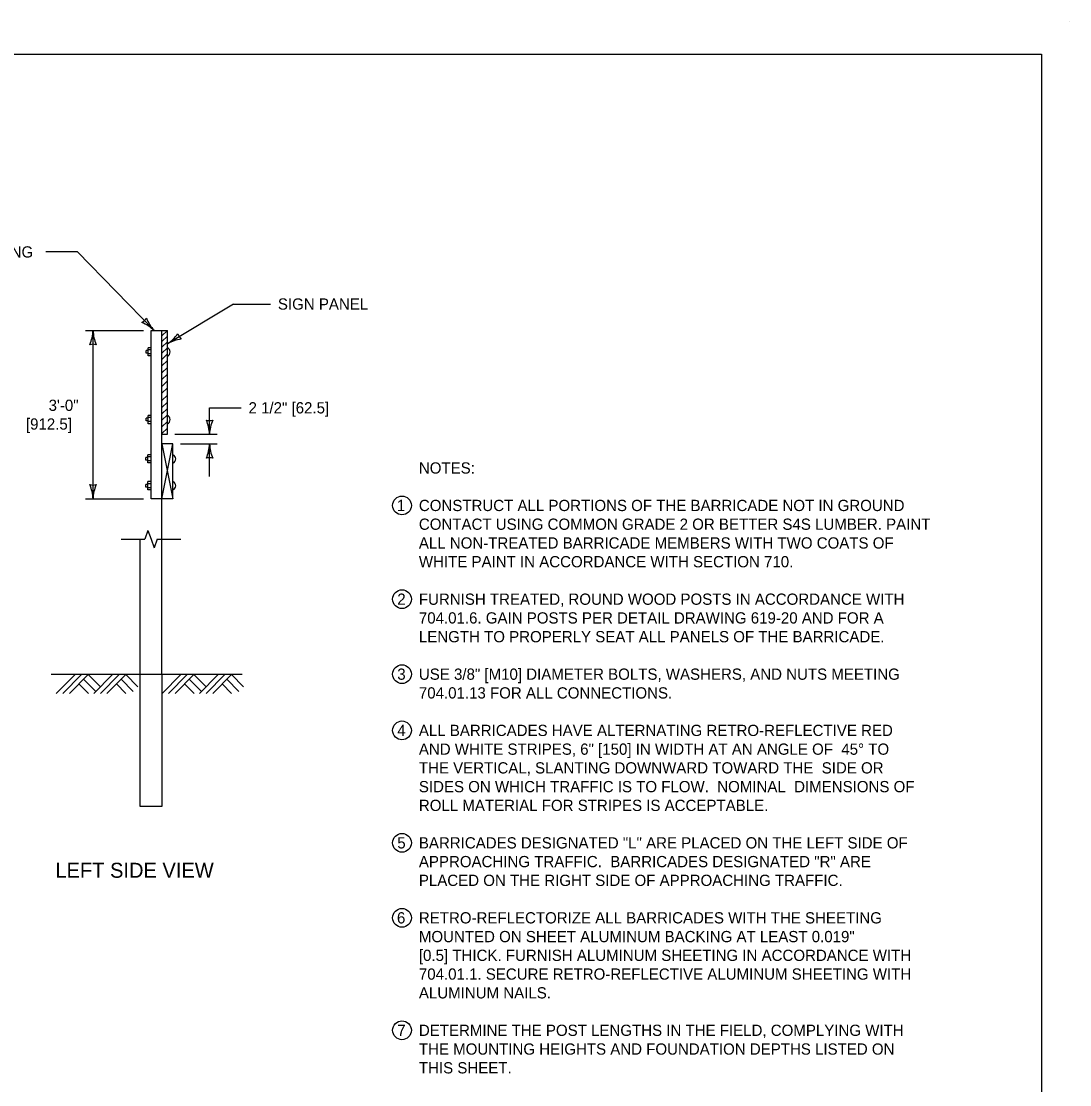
# Model space of a CAD drawing. Extents: x 49991.4 to 50021, y 49987.6 to 50011.4.
# Drawn here: x 50011.31 to 50016.9, y 49993.5 to 49999.18 of the extents above; entities that cross this region are included whole.
import ezdxf

# ---------------------------------------------------------------- set-up
doc = ezdxf.new("R2010")
doc.units = 0
for name, color, linetype in [('Level 1', 7, 'Continuous'), ('Level 2', 7, 'Continuous'), ('Level 3', 7, 'Continuous'), ('Level 4', 7, 'Continuous'), ('Level 6', 7, 'Continuous')]:
    doc.layers.add(name, color=color, linetype=linetype)

msp = doc.modelspace()

# ---------------------------------------------------------------- linework, layer by layer
at = {"layer": 'Level 1'}
for p, q in [((50016.9001, 49999.1756), (50016.9001, 49999.1756)), ((50012.0001, 49997.5261), (50012.0874, 49997.5261)), ((50012.0001, 49996.6277), (50012.0001, 49997.5261)), ((50012.0586, 49996.9206), (50012.0586, 49997.5261)), ((50012.0874, 49997.5261), (50012.0586, 49997.4973)), ((50012.0874, 49996.9724), (50012.0874, 49997.5261)), ((50012.0874, 49997.4958), (50012.0586, 49997.467)), ((50012.0874, 49997.4658), (50012.0586, 49997.437)), ((50011.9738, 49997.4045), (50011.9738, 49997.4195)), ((50011.9852, 49997.4195), (50011.9738, 49997.4195)), ((50011.9852, 49997.4045), (50011.9738, 49997.4045)), ((50012.0001, 49997.434), (50011.9852, 49997.434)), ((50011.9852, 49997.39), (50011.9852, 49997.434)), ((50012.0001, 49997.423), (50011.9852, 49997.423)), ((50012.0001, 49997.401), (50011.9852, 49997.401)), ((50012.0001, 49997.39), (50011.9852, 49997.39)), ((50012.0874, 49997.4329), (50012.0586, 49997.4041)), ((50012.0874, 49997.4005), (50012.0586, 49997.3717)), ((50012.0874, 49997.3658), (50012.0586, 49997.337)), ((50012.0874, 49997.3282), (50012.0586, 49997.2994)), ((50012.0874, 49997.2924), (50012.0586, 49997.2636)), ((50012.0874, 49997.2565), (50012.0586, 49997.2277)), ((50012.0874, 49997.2196), (50012.0586, 49997.1908)), ((50012.0874, 49997.1814), (50012.0586, 49997.1526)), ((50012.0874, 49997.1444), (50012.0586, 49997.1156)), ((50012.0874, 49997.1106), (50012.0586, 49997.0818)), ((50011.9738, 49997.0433), (50011.9738, 49997.0583)), ((50011.9852, 49997.0583), (50011.9738, 49997.0583)), ((50012.0001, 49997.0728), (50011.9852, 49997.0728)), ((50011.9852, 49997.0288), (50011.9852, 49997.0728)), ((50012.0001, 49997.0618), (50011.9852, 49997.0618)), ((50012.0874, 49997.0763), (50012.0586, 49997.0475)), ((50011.9852, 49997.0433), (50011.9738, 49997.0433)), ((50012.0001, 49997.0398), (50011.9852, 49997.0398)), ((50012.0001, 49997.0288), (50011.9852, 49997.0288)), ((50012.0874, 49997.0406), (50012.0586, 49997.0118)), ((50012.0876, 49997.0052), (50012.0586, 49996.9762)), ((50012.0586, 49996.9724), (50012.0874, 49996.9724)), ((50012.0586, 49996.6277), (50012.1172, 49996.9206)), ((50012.0586, 49996.9206), (50012.1172, 49996.6277)), ((50012.0586, 49995.6901), (50012.0586, 49996.9206)), ((50012.1172, 49996.9206), (50012.0586, 49996.9206)), ((50012.1172, 49996.6277), (50012.1172, 49996.9206)), ((50011.9726, 49996.8336), (50011.9726, 49996.8486)), ((50011.984, 49996.8486), (50011.9726, 49996.8486)), ((50011.984, 49996.8336), (50011.9726, 49996.8336)), ((50012.0001, 49996.8631), (50011.984, 49996.8631)), ((50011.984, 49996.8191), (50011.984, 49996.8631)), ((50012.0001, 49996.8521), (50011.984, 49996.8521)), ((50012.0001, 49996.8301), (50011.984, 49996.8301)), ((50012.0001, 49996.8191), (50011.984, 49996.8191)), ((50012.0001, 49996.7196), (50011.984, 49996.7196)), ((50011.984, 49996.6756), (50011.984, 49996.7196)), ((50012.0001, 49996.7086), (50011.984, 49996.7086)), ((50011.9726, 49996.6901), (50011.9726, 49996.7051)), ((50011.984, 49996.7051), (50011.9726, 49996.7051)), ((50011.984, 49996.6901), (50011.9726, 49996.6901)), ((50012.0001, 49996.6866), (50011.984, 49996.6866)), ((50012.0001, 49996.6756), (50011.984, 49996.6756)), ((50012.1172, 49996.6277), (50012.0001, 49996.6277)), ((50011.9415, 49995.6901), (50011.9415, 49996.4123)), ((50012.4865, 49995.6901), (50011.4678, 49995.6901)), ((50011.4951, 49995.5901), (50011.5951, 49995.6901)), ((50011.5301, 49995.5901), (50011.6301, 49995.6901)), ((50011.5651, 49995.5901), (50011.6651, 49995.6901)), ((50011.6651, 49995.6901), (50011.7301, 49995.6251)), ((50011.6951, 49995.5901), (50011.7951, 49995.6901)), ((50011.7301, 49995.5901), (50011.8301, 49995.6901)), ((50011.7651, 49995.5901), (50011.8651, 49995.6901)), ((50011.8651, 49995.6901), (50011.9301, 49995.6251)), ((50012.0588, 49995.5901), (50012.1588, 49995.6901)), ((50012.0938, 49995.5901), (50012.1938, 49995.6901)), ((50012.1288, 49995.5901), (50012.2288, 49995.6901)), ((50012.2288, 49995.6901), (50012.2938, 49995.6251)), ((50012.259, 49995.5901), (50012.359, 49995.6901)), ((50012.294, 49995.5901), (50012.394, 49995.6901)), ((50012.329, 49995.5901), (50012.429, 49995.6901)), ((50012.429, 49995.6901), (50012.494, 49995.6251)), ((50011.6156, 49995.6406), (50011.6661, 49995.5901)), ((50011.6404, 49995.6654), (50011.7054, 49995.6004)), ((50011.8156, 49995.6406), (50011.8661, 49995.5901)), ((50011.8404, 49995.6654), (50011.9054, 49995.6004)), ((50012.1793, 49995.6406), (50012.2298, 49995.5901)), ((50012.2041, 49995.6654), (50012.2691, 49995.6004)), ((50012.3795, 49995.6406), (50012.43, 49995.5901)), ((50012.4043, 49995.6654), (50012.4693, 49995.6004))]:
    msp.add_line(p, q, dxfattribs=at)
msp.add_lwpolyline([(49999.3835, 49998.9992), (50016.7501, 49998.9992), (50016.7501, 49987.7988), (49999.3835, 49987.7988)], close=True, dxfattribs=at)
for centre in [(50012.0779, 49997.4113), (50012.0779, 49997.0502), (50012.1077, 49996.8405), (50012.1077, 49996.698)]:
    msp.add_arc(centre, 0.0243, 292.9563, 67.0437, dxfattribs=at)
at = {"layer": 'Level 2'}
for centre in [(50013.3387, 49996.5925), (50013.3387, 49996.0925), (50013.3387, 49995.6925), (50013.3387, 49995.3925), (50013.3387, 49994.7925), (50013.3387, 49994.3925), (50013.3387, 49993.7925)]:
    msp.add_circle(centre, 0.0501, dxfattribs=at)
at = {"layer": 'Level 3'}
for p, q in [((50011.608, 49997.945), (50011.4399, 49997.945)), ((50011.608, 49997.945), (50012.0161, 49997.5261)), ((50012.4403, 49997.6671), (50012.0874, 49997.4553)), ((50012.4403, 49997.6671), (50012.6369, 49997.6671)), ((50011.6508, 49997.5261), (50011.9601, 49997.5261)), ((50011.6908, 49996.6277), (50011.6908, 49997.5261)), ((50012.3123, 49996.9723), (50012.3123, 49997.1134)), ((50012.3123, 49997.1134), (50012.4803, 49997.1134)), ((50012.1274, 49996.9723), (50012.3523, 49996.9723)), ((50012.1572, 49996.9205), (50012.3523, 49996.9205)), ((50012.3123, 49996.7471), (50012.3123, 49996.9205)), ((50012.3123, 49996.8747), (50012.3123, 49996.875)), ((50011.6508, 49996.6277), (50011.9601, 49996.6277))]:
    msp.add_line(p, q, dxfattribs=at)
for centre, radius, start, end in [((50011.9266, 49997.6179), 0.0548, 296.3915, 332.1138), ((50011.8574, 49997.3555), 0.233, 47.0799, 66.3298), ((50012.1816, 49997.6746), 0.2223, 201.7086, 221.8922), ((50011.4687, 49997.5353), 0.2223, 337.456, 357.6395), ((50011.9235, 49997.5376), 0.233, 182.8273, 202.0772), ((50011.9578, 49997.6489), 0.233, 303.7958, 323.0457), ((50012.1973, 49997.5213), 0.0548, 193.1073, 228.8297), ((50011.6908, 49997.3979), 0.0548, 72.1388, 107.8612), ((50012.1939, 49997.2601), 0.2223, 98.4245, 118.608), ((50012.3123, 49997.1005), 0.0548, 252.1388, 287.8612), ((50012.0796, 49996.9608), 0.233, 2.8273, 22.0772), ((50012.5344, 49996.9631), 0.2223, 157.456, 177.6395), ((50012.0902, 49996.9297), 0.2223, 337.456, 357.6395), ((50012.545, 49996.932), 0.233, 182.8273, 202.0772), ((50012.3123, 49996.7923), 0.0548, 72.1388, 107.8612), ((50011.6908, 49996.7559), 0.0548, 252.1388, 287.8612), ((50011.4581, 49996.6162), 0.233, 2.8273, 22.0772), ((50011.9129, 49996.6185), 0.2223, 157.456, 177.6395)]:
    msp.add_arc(centre, radius, start, end, dxfattribs=at)
at = {"layer": 'Level 4'}
for p, q in [((50011.9415, 49994.987), (50011.9415, 49995.6901)), ((50012.0586, 49995.6901), (50012.0586, 49994.987)), ((50012.0586, 49994.987), (50011.9415, 49994.987))]:
    msp.add_line(p, q, dxfattribs=at)
at = {"layer": 'Level 6'}
for p, q in [((50011.9839, 49996.458), (50011.9677, 49996.4123)), ((50011.9839, 49996.458), (50012.0001, 49996.4123)), ((50011.8415, 49996.4123), (50011.9677, 49996.4123)), ((50012.0001, 49996.4123), (50012.0163, 49996.3666)), ((50012.0325, 49996.4123), (50012.0163, 49996.3666)), ((50012.0325, 49996.4123), (50012.1586, 49996.4123))]:
    msp.add_line(p, q, dxfattribs=at)

# ---------------------------------------------------------------- texts
at = {"layer": 'Level 2'}
for s, height, p in [('BACKBRACING', 0.06, (50010.7878, 49997.915)), ('SIGN PANEL', 0.06, (50012.6769, 49997.6371)), ('3\'-0"', 0.06, (50011.4539, 49997.0969)), ('2 1/2" [62.5]', 0.06, (50012.5203, 49997.0834)), ('[912.5]', 0.06, (50011.3329, 49996.9969)), ('NOTES:', 0.06, (50013.4288, 49996.7625)), ('1', 0.06, (50013.3113, 49996.5626)), ('CONSTRUCT ALL PORTIONS OF THE BARRICADE NOT IN GROUND ', 0.06, (50013.4288, 49996.5625)), ('CONTACT USING COMMON GRADE 2 OR BETTER S4S LUMBER. PAINT ', 0.06, (50013.4288, 49996.4625)), ('ALL NON-TREATED BARRICADE MEMBERS WITH TWO COATS OF ', 0.06, (50013.4288, 49996.3625)), ('WHITE PAINT IN ACCORDANCE WITH SECTION 710.', 0.06, (50013.4288, 49996.2625)), ('2', 0.06, (50013.3135, 49996.0625)), ('FURNISH TREATED, ROUND WOOD POSTS IN ACCORDANCE WITH ', 0.06, (50013.4288, 49996.0625)), ('704.01.6. GAIN POSTS PER DETAIL DRAWING 619-20 AND FOR A ', 0.06, (50013.4288, 49995.9625)), ('LENGTH TO PROPERLY SEAT ALL PANELS OF THE BARRICADE.', 0.06, (50013.4288, 49995.8625)), ('3', 0.06, (50013.3135, 49995.6625)), ('USE 3/8" [M10] DIAMETER BOLTS, WASHERS, AND NUTS MEETING ', 0.06, (50013.4288, 49995.6625)), ('704.01.13 FOR ALL CONNECTIONS.', 0.06, (50013.4288, 49995.5625)), ('4', 0.06, (50013.3135, 49995.3625)), ('ALL BARRICADES HAVE ALTERNATING RETRO-REFLECTIVE RED ', 0.06, (50013.4288, 49995.3625)), ('AND WHITE STRIPES, 6" [150] IN WIDTH AT AN ANGLE OF  45° TO ', 0.06, (50013.4288, 49995.2625)), ('THE VERTICAL, SLANTING DOWNWARD TOWARD THE  SIDE OR ', 0.06, (50013.4288, 49995.1625)), ('SIDES ON WHICH TRAFFIC IS TO FLOW.  NOMINAL  DIMENSIONS OF ', 0.06, (50013.4288, 49995.0625)), ('ROLL MATERIAL FOR STRIPES IS ACCEPTABLE.', 0.06, (50013.4288, 49994.9625)), ('5', 0.06, (50013.3135, 49994.7625)), ('BARRICADES DESIGNATED "L" ARE PLACED ON THE LEFT SIDE OF ', 0.06, (50013.4288, 49994.7625)), ('APPROACHING TRAFFIC.  BARRICADES DESIGNATED "R" ARE ', 0.06, (50013.4288, 49994.6625)), ('LEFT SIDE VIEW', 0.08, (50011.4904, 49994.6062)), ('PLACED ON THE RIGHT SIDE OF APPROACHING TRAFFIC.', 0.06, (50013.4288, 49994.5625)), ('6', 0.06, (50013.3118, 49994.3625)), ('RETRO-REFLECTORIZE ALL BARRICADES WITH THE SHEETING ', 0.06, (50013.4288, 49994.3625)), ('MOUNTED ON SHEET ALUMINUM BACKING AT LEAST 0.019" ', 0.06, (50013.4288, 49994.2625)), ('[0.5] THICK. FURNISH ALUMINUM SHEETING IN ACCORDANCE WITH ', 0.06, (50013.4288, 49994.1625)), ('704.01.1. SECURE RETRO-REFLECTIVE ALUMINUM SHEETING WITH ', 0.06, (50013.4288, 49994.0625)), ('ALUMINUM NAILS.', 0.06, (50013.4288, 49993.9625)), ('7', 0.06, (50013.3135, 49993.7625)), ('DETERMINE THE POST LENGTHS IN THE FIELD, COMPLYING WITH ', 0.06, (50013.4288, 49993.7625)), ('THE MOUNTING HEIGHTS AND FOUNDATION DEPTHS LISTED ON ', 0.06, (50013.4288, 49993.6625)), ('THIS SHEET.', 0.06, (50013.4288, 49993.5625))]:
    msp.add_text(s, height=height, dxfattribs=at).set_placement(p)

doc.saveas('drawing.dxf')
